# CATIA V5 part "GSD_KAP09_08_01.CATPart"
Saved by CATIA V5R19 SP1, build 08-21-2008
Part number: GSD_REPETITION_07
Description: Beispielmodell. PowerCopy erzeugen  Maik Hertha IT Consultants
Bounding box of the stored display mesh (mm): x -29.841 to 13.746, y -10 to 40, z 36.232 to 53.986
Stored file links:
  \GSD_BUCH_UEBUNG\GSD_KAP09_08_01.CATPart
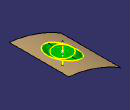
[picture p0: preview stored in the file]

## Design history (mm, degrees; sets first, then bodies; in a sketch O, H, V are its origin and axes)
AxisSystem1 "Absolute Axis System": origin (0, 0, 0), X (1, 0, 0), Y (0, 1, 0), Z (0, 0, 1)
Set1 "Referenz_PC"
  Line1 "Ausrichtung": stored without definition
  DatumSurface1 "Referenzflaeche"
  Intersect1 "Referenzpunkt": ToIntersect1 DatumSurface1, ToIntersect2 Line1
  Set2 "Template"
    Plane1: type Normal, Curve Line1, RefPoint Intersect1
    Sketch1 on Plane1, origin (-6.428, 14.4636, 46.9865), H (0, -1, 0), V (1, 0, 0)
      circle A1 centre (0, 0) radius 7.5
      radius A1 = 7.5
    Split1: ToCut Plane1, Intersections {intersect ToIntersect1 Plane1, ToIntersect2 Sketch1}, Cutting Sketch1
    Extrude1: Lim1 13, Lim2 13, Element1 Sketch1, Direction Plane1
    Offset1: Length 5, Offset Extrude1
    Split2: ToCut DatumSurface1, Intersections {intersect ToIntersect1 DatumSurface1, ToIntersect2 Offset1}, Cutting Offset1
    Blend1: StartLimit {blendlimit Support Split1, Curve {intersect ToIntersect1 Plane1, ToIntersect2 Sketch1}, Point {extremum Reference {intersect ToIntersect1 Plane1, ToIntersect2 Sketch1}, Direction2 (0, 0, 1), Direction3 (0, 0, 1), Direction (0, 1, 0)}}, EndLimit {blendlimit Support Split2, Curve {intersect ToIntersect1 DatumSurface1, ToIntersect2 Offset1}, Point {extremum Reference {intersect ToIntersect1 DatumSurface1, ToIntersect2 Offset1}, Direction2 (0, 0, 1), Direction3 (0, 0, 1), Direction (0, 1, 0)}}
Body1 (main body)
